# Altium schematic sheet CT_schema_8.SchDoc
size 280 x 153 mm
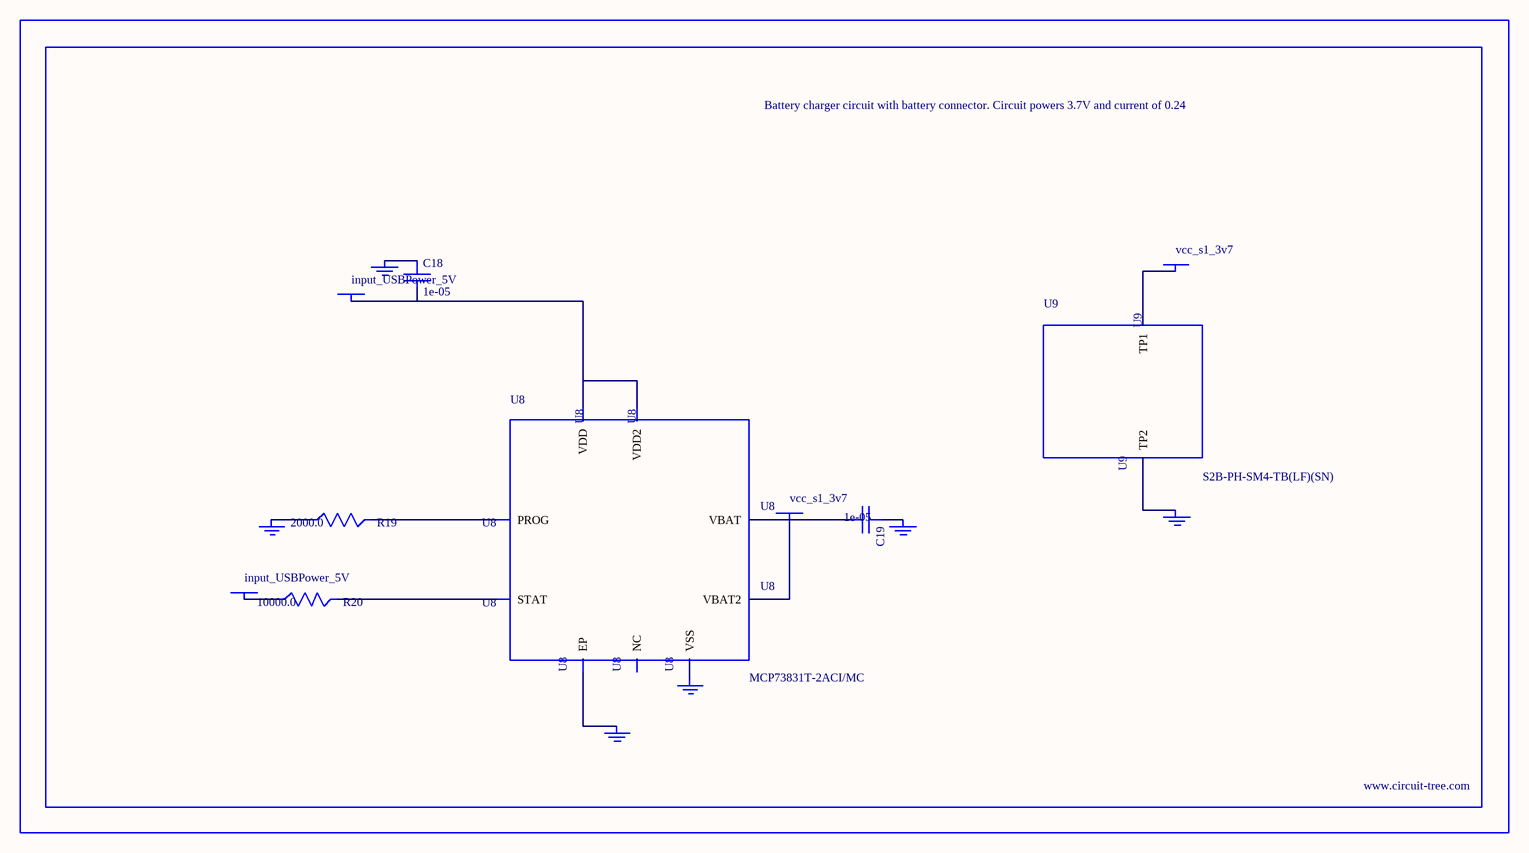
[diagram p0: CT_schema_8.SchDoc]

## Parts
BORDER7  (no value)
C18  1e-05  [C1206]
C19  1e-05  [C1206]
GND_INSTANCE_7_0  (no value)
GND_INSTANCE_7_1  (no value)
GND_INSTANCE_7_2  (no value)
GND_INSTANCE_7_3  (no value)
GND_INSTANCE_7_4  (no value)
GND_INSTANCE_7_5  (no value)
POWER_INSTANCE_7_0  input_USBPower_5V
POWER_INSTANCE_7_1  input_USBPower_5V
POWER_INSTANCE_7_2  vcc_s1_3v7
POWER_INSTANCE_7_3  vcc_s1_3v7
R19  2000.0  [R0603]
R20  10000.0  [R0603]
U8  MCP73831T-2ACI/MC  [DFN8_2X3MC]
U9  S2B-PH-SM4-TB(LF)(SN)  [JST-2-SMD]

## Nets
NetC18_1: C18.1 GND_INSTANCE_7_0.0(GND)
NetC18_2: C18.2 POWER_INSTANCE_7_0.0(PWR) U8.1(VDD) U8.2(VDD2)
NetC19_1: C19.1 GND_INSTANCE_7_1.0(GND)
NetC19_2: C19.2 POWER_INSTANCE_7_2.0(PWR) U8.3(VBAT) U8.4(VBAT2)
NetGND_INSTANCE_7_2_0: GND_INSTANCE_7_2.0(GND) R19.1
NetGND_INSTANCE_7_3_0: GND_INSTANCE_7_3.0(GND) U8.9(EP)
NetGND_INSTANCE_7_4_0: GND_INSTANCE_7_4.0(GND) U8.6(VSS)
NetGND_INSTANCE_7_5_0: GND_INSTANCE_7_5.0(GND) U9.2(TP2)
NetPOWER_INSTANCE_7_1_0: POWER_INSTANCE_7_1.0(PWR) R20.1
NetPOWER_INSTANCE_7_3_0: POWER_INSTANCE_7_3.0(PWR) U9.1(TP1)
NetR19_2: R19.2 U8.8(PROG)
NetR20_2: R20.2 U8.5(STAT)

Not connected (* = marked no-connect by the designer): U8 7(NC)

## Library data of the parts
BORDER7 = BORDER_PAGE7
C18 C19 = C1206C106K3RACTU
GND_INSTANCE_7_0-GND_INSTANCE_7_5 = GND
POWER_INSTANCE_7_0-POWER_INSTANCE_7_3 = PWR
R19 = RC0603JR-072KL
R20 = RC0603JR-0710KL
